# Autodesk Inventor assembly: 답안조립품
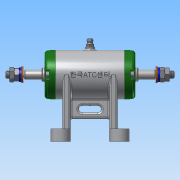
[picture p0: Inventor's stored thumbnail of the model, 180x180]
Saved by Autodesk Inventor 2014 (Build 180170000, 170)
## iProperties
Created: 2007-09
Part Number: 답안조립품
Document SubType Name: Assembly
Designer: 103-28
Author: 103-28
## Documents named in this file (16)
- C:\Users\103-28\Desktop\451110V1012\답안조립품.iam
- C:\Users\103-28\Desktop\451110V1012\1-본체.ipt
- C:\Users\103-28\Desktop\451110V1012\니플 M 6 x 0.75.ipt
- C:\Users\103-28\Desktop\451110V1012\볼트 M 6 x 8.ipt
- C:\Users\103-28\Desktop\451110V1012\와셔 6x11.5.ipt
- C:\Users\103-28\Desktop\451110V1012\스프링와셔 8.ipt
- C:\Users\103-28\Desktop\451110V1012\와셔 8x17.ipt
- C:\Users\103-28\Desktop\451110V1012\V벨트풀리.ipt
- C:\Users\103-28\Desktop\451110V1012\스퍼기어.ipt
- C:\Users\103-28\Desktop\451110V1012\키 3 x 3 x 12.ipt
- C:\Users\103-28\Desktop\451110V1012\베어링 15 x 32 x 9.ipt
- C:\Users\103-28\Desktop\451110V1012\축.ipt
- C:\Users\103-28\Desktop\451110V1012\커버.ipt
- C:\Users\103-28\Desktop\451110V1012\오일 실 15 25 7.ipt
- C:\Users\103-28\Desktop\451110V1012\너트 M 8.ipt
- C:\Users\103-28\Desktop\451110V1012\볼트 M4 x 12.ipt
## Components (12 placed, 4 different names)
1. 1-본체:1
2. V벨트풀리:1 — 각도:3
3. KS B 2023 6002 - 15 x 32 x 9:1
4. KS B 2023 6002 - 15 x 32 x 9:2
5. ISO 4762 M4 x 12:2
6. ISO 4762 M4 x 12:3
7. ISO 4762 M4 x 12:4
8. ISO 4762 M4 x 12:5
9. ISO 4762 M4 x 12:1
10. ISO 4762 M4 x 12:6
11. ISO 4762 M4 x 12:7
12. ISO 4762 M4 x 12:8
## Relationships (1: Angle 1)
- 각도:3 [Angle]: V벨트풀리:1
